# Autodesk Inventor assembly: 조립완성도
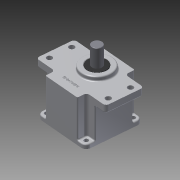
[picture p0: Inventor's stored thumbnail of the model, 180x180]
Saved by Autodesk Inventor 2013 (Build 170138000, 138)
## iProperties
Created: 2015-07
Part Number: 조립완성도
Document SubType Name: Assembly
Designer: user
Author: user
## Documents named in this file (12)
- C:\Users\user\Desktop\450734V1003\조립완성도.iam
- C:\Users\user\Desktop\450734V1003\메인축.ipt
- C:\Users\user\Desktop\450734V1003\베어링 608.ipt
- 베어링 608.ipt
- C:\Users\user\Desktop\450734V1003\본체.ipt
- C:\Users\user\Desktop\450734V1003\서브축.ipt
- C:\Users\user\Desktop\450734V1003\베어링 6003.ipt
- 베어링 6003.ipt
- C:\Users\user\Desktop\450734V1003\오일실 17x32x8.ipt
- C:\Users\user\Desktop\450734V1003\커버.ipt
- C:\Users\user\Desktop\450734V1003\오일실 8x22x7.ipt
- C:\Users\user\Desktop\450734V1003\M4x0.5x16.ipt
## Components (4 placed, 1 different names)
1. M4x0.5x12:1
2. M4x0.5x12:2
3. M4x0.5x12:3
4. M4x0.5x12:4
